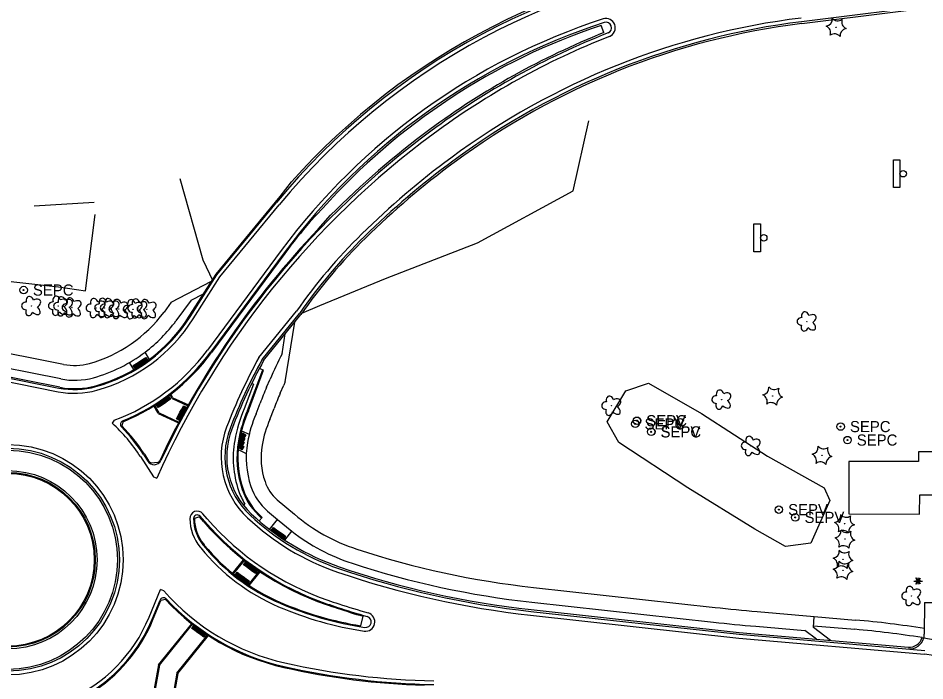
# Model space of a CAD drawing. Extents: x 588843 to 2552415, y 180129 to 269402.
# Drawn here: x 590641.6 to 591129.5, y 186685.9 to 187042.7 of the extents above; entities that cross this region are included whole.
import ezdxf

# ---------------------------------------------------------------- set-up
doc = ezdxf.new("R2010")
doc.units = 0
for name, color, linetype in [('E_BLD', 7, 'Continuous'), ('E_LAND_TreeLine', 7, 'Continuous'), ('E_LAND_Vegetation', 7, 'Continuous'), ('E_LTG', 7, 'Continuous'), ('E_MISCPROP_Septic', 7, 'Continuous'), ('E_MISCPROP_YardLight', 7, 'Continuous'), ('E_RDWY_Gravel', 7, 'Continuous'), ('E_SGN', 7, 'Continuous'), ('P_DWY', 7, 'Continuous'), ('P_PATH_Sidewalk', 7, 'Continuous'), ('P_RDWY_C_and_G_30', 7, 'Continuous'), ('P_RDWY_C_and_G_36', 7, 'Continuous'), ('P_RDWY_C_and_GBack', 7, 'Continuous'), ('P_RDWY_C_and_GFace', 7, 'Continuous'), ('P_RDWY_LaneEdge', 7, 'Continuous')]:
    doc.layers.add(name, color=color, linetype=linetype)

# ---------------------------------------------------------------- blocks, each defined once
blk = doc.blocks.new('CTRE_2')
at = {"layer": 'E_LAND_Vegetation'}
blk.add_circle((0, 0), 0.223, dxfattribs=at)
for centre, start, end in [((-11.97, 8.96), 280.2067, 5.97162), ((1.81, 14.92), 220.21132, 305.97623), ((-13.83, -5.9), 340.21132, 65.97623), ((13.83, 5.89), 160.21133, 245.97624), ((-1.81, -14.93), 40.21133, 125.97624), ((12.03, -9.04), 100.25111, 185.92721)]:
    blk.add_arc(centre, 7.87, start, end, dxfattribs=at)
blk = doc.blocks.new('DTRE_2')
at = {"layer": 'E_LAND_Vegetation'}
blk.add_circle((-0.18, 0), 0.183, dxfattribs=at)
for centre, major_axis, ratio in [((-1.87, 5.32), (1.36, -4.98), 0.782863), ((-5.87, 0.15), (4.93, -0.12), 0.832022), ((4.06, 2.74), (-5.27, -2.93), 0.691916), ((-2.49, -5.24), (1.8, 4.86), 0.716896), ((3.54, -3.71), (-5.01, 4.58), 0.560249)]:
    blk.add_ellipse(centre, major_axis=major_axis, ratio=ratio, start_param=1.570796, end_param=4.712389, dxfattribs=at)
blk = doc.blocks.new('LPOL_2')
at = {"layer": 'E_LTG'}
for p, q in [((-4, 0), (-1.5, 0)), ((-0.75, 1.3), (-2, 3.46)), ((0.75, 1.3), (2, 3.46)), ((1.5, 0), (4, 0)), ((-2, -3.46), (-0.75, -1.3)), ((2, -3.46), (0.75, -1.3))]:
    blk.add_line(p, q, dxfattribs=at)
for radius in [1.5, 1.5, 1.5, 0.125]:
    blk.add_circle((0, 0), radius, dxfattribs=at)
blk = doc.blocks.new('SEPC')
at = {"layer": 'E_MISCPROP_Septic'}
for radius in [4, 0.5]:
    blk.add_circle((0, 0), radius, dxfattribs=at)
blk.add_text('SEPC', height=12, dxfattribs=at).set_placement((10, -6))
blk = doc.blocks.new('SEPV')
at = {"layer": 'E_MISCPROP_Septic'}
for radius in [4, 0.5]:
    blk.add_circle((0, 0), radius, dxfattribs=at)
blk.add_text('SEPV', height=12, dxfattribs=at).set_placement((10, -6))
blk = doc.blocks.new('SGN')
at = {"layer": 'E_SGN'}
blk.add_lwpolyline([(-3.5, -15), (-10.5, -15), (-10.5, 15), (-3.5, 15)], close=True, dxfattribs=at)
blk.add_circle((0, 0), 3.5, dxfattribs=at)
blk = doc.blocks.new('RAMPD_1')
at = {"layer": 'P_PATH_Sidewalk'}
for p, q in [((-0.01, 0), (-0.01, 0.02)), ((-0.01, 0.02), (0.01, 0.02)), ((0.01, 0), (-0.01, 0)), ((0.01, 0.02), (0.01, 0))]:
    blk.add_line(p, q, dxfattribs=at)
for centre in [(-0.0075, 0.0175), (-0.0075, 0.0137), (-0.0075, 0.01), (-0.0075, 0.0062), (-0.0075, 0.0025), (-0.0037, 0.0175), (-0.0037, 0.0137), (-0.0037, 0.01), (-0.0037, 0.0062), (-0.0037, 0.0025), (0, 0.0175), (0, 0.0137), (0, 0.01), (0, 0.0062), (0, 0.0025), (0.0038, 0.0175), (0.0038, 0.0137), (0.0038, 0.01), (0.0038, 0.0062), (0.0038, 0.0025), (0.0075, 0.0175), (0.0075, 0.0137), (0.0075, 0.01), (0.0075, 0.0062), (0.0075, 0.0025)]:
    blk.add_circle(centre, 0.00125, dxfattribs=at)

msp = doc.modelspace()

# ---------------------------------------------------------------- linework, layer by layer
at = {"layer": 'E_BLD'}
msp.add_lwpolyline([(590682.52, 186943.34), (590650.19, 186941.49)], dxfattribs=at)
msp.add_lwpolyline([(591142.19, 186809.23), (591126.11, 186809.29), (591126.08, 186804), (591088.64, 186804.02), (591088.48, 186775.91), (591088.48, 186775.9), (591126.66, 186775.73), (591126.73, 186786), (591142.01, 186786.04)], close=True, dxfattribs=at)
at = {"layer": 'E_LAND_TreeLine'}
for points in [[(590794.26, 186883.86), (590804, 186888.02), (590839.27, 186902.57), (590888.67, 186921.7), (590940.25, 186949.76), (590948.66, 186987.38)], [(590728.5, 186956.4), (590740.87, 186912.64), (590746.29, 186901.31)]]:
    msp.add_lwpolyline(points, dxfattribs=at)
at = {"layer": 'E_MISCPROP_Septic'}
msp.add_lwpolyline([(591037.97, 186767.55), (591001.85, 186789.88), (590964.8, 186814.16), (590958.54, 186825.27), (590968.64, 186842.04), (590980.73, 186846.16), (591009.2, 186829.87), (591044.76, 186806.95), (591075.3, 186789.75), (591078.29, 186783.05), (591068.19, 186760.11), (591054.5, 186758.23)], close=True, dxfattribs=at)
at = {"layer": 'E_RDWY_Gravel'}
msp.add_lwpolyline([(590503.84, 186888.11), (590515.32, 186892.37), (590571.93, 186894.96), (590593.36, 186895.68), (590629.65, 186901.83), (590663.34, 186898.08), (590677.82, 186895.83), (590683.07, 186936.89)], dxfattribs=at)
at = {"layer": 'P_DWY'}
for points in [[(591129.19, 186728.06), (591129.18, 186711.06)], [(591129.19, 186728.06), (591141.11, 186728.08)], [(591128.92, 186709.05), (591141.16, 186706.9)]]:
    msp.add_lwpolyline(points, dxfattribs=at)
for start, end in [(265.0417, 345.4333), (345.4333, 359.9711)]:
    msp.add_arc((591121.18, 186711.06), 8, start, end, dxfattribs=at)
at = {"layer": 'P_PATH_Sidewalk'}
for p, q in [((590723.97, 186889.71), (590745.63, 186901.04)), ((590734.75, 186890.83), (590741.35, 186894.28)), ((590785.28, 186846.98), (590790.37, 186878.96)), ((590783.61, 186861.94), (590785.33, 186872.75)), ((590712.18, 186858.98), (590709.9, 186862.9)), ((590703.83, 186853.45), (590701.57, 186857.34)), ((590724.43, 186837.96), (590723.29, 186839.92)), ((590724.43, 186837.96), (590732.91, 186834.02)), ((590717.37, 186830.22), (590715.05, 186834.19)), ((590717.37, 186830.22), (590728.12, 186825.22)), ((590761.78, 186820.6), (590765.93, 186818.66)), ((590759.98, 186810.4), (590764.36, 186808.37)), ((590781.01, 186783.45), (590790.23, 186775.62)), ((590775.83, 186777.35), (590781.18, 186772.81)), ((590776.86, 186767.48), (590781.18, 186772.81)), ((590785.03, 186761.68), (590788.88, 186766.42)), ((590757.37, 186743.46), (590763.31, 186750.78)), ((590765.43, 186737.52), (590771.43, 186744.91)), ((591069.46, 186714.61), (591069.86, 186720.6)), ((590717.58, 186694.4), (590735.4, 186716.38)), ((591078.78, 186707.71), (591069.46, 186714.61)), ((590726.97, 186690.11), (590743.55, 186710.55)), ((591071.16, 186708.38), (591064.91, 186713)), ((590717.58, 186694.4), (590712.48, 186665.67)), ((590726.97, 186690.11), (590722.35, 186664.07))]:
    msp.add_line(p, q, dxfattribs=at)
for points in [[(590723.97, 186889.71), (590720.08, 186884.45)], [(590734.75, 186890.83), (590726.51, 186879.69)], [(590666.03, 186856.29), (590573.06, 186874.79)], [(590664.47, 186848.45), (590664.47, 186848.45), (590570.02, 186867.24)], [(590775.26, 186843.97), (590777.12, 186848.29)], [(590782.6, 186840.8), (590784.47, 186845.12)], [(590769.61, 186829.63), (590771.78, 186835.36)], [(590777.03, 186826.62), (590779.26, 186832.53)], [(590781.18, 186772.81), (590788.88, 186766.42)], [(590918.87, 186736.23), (591016.58, 186725.48)], [(590918, 186728.27), (591015.71, 186717.53)], [(591039.25, 186723.26), (591069.86, 186720.6)], [(591069.86, 186720.6), (591092.2, 186718.66)], [(591038.56, 186715.29), (591064.91, 186713)], [(591069.52, 186715.61), (591091.77, 186713.68)]]:
    msp.add_lwpolyline(points, dxfattribs=at)
for centre, radius, start, end in [((590659.79, 186929.06), 75, 285.593, 323.5041), ((590659.79, 186929.06), 83, 307.1416, 323.5041), ((590659.79, 186929.06), 83, 285.593, 307.1416), ((590968.1, 186765.87), 208, 152.491, 156.6561), ((590671.89, 186885.72), 30, 258.747, 285.593), ((590671.89, 186885.72), 38, 258.747, 285.593), ((590968.1, 186765.87), 200, 156.0748, 156.6561), ((590958.89, 186764.72), 200, 156.6561, 159.3176), ((590958.89, 186764.72), 192, 156.6561, 159.3176), ((590832, 186802.58), 68, 156.56, 170.1686), ((590832, 186802.58), 60, 156.3818, 170.1686), ((590812.3, 186806), 48, 170.1684, 198.7153), ((590812.3, 186806), 40, 170.1684, 198.7153), ((590795.25, 186800.22), 22, 198.7153, 229.669), ((590795.25, 186800.22), 30, 198.7153, 229.669), ((590854.95, 186851.85), 100, 229.669, 251.8118), ((590854.95, 186851.85), 108, 232.2824, 251.8118), ((590970.13, 187202.42), 469, 251.8118, 263.7259), ((590970.13, 187202.42), 477, 251.8118, 263.7259), ((591124.99, 187711.54), 992, 263.72585, 265.04172), ((591048.56, 186215.55), 505, 80.8131, 85.0417), ((591124.99, 187711.54), 1000, 263.72585, 265.04172), ((591048.56, 186215.55), 500, 80.8657, 85.0417)]:
    msp.add_arc(centre, radius, start, end, dxfattribs=at)
at = {"layer": 'P_RDWY_C_and_G_30'}
for p, q in [((590741.43, 186771.53), (590739.08, 186774.25)), ((590772.92, 186773.92), (590771.29, 186772.02)), ((590756.99, 186743.78), (590762.92, 186751.09)), ((590765.85, 186737.24), (590771.84, 186744.63)), ((590714.31, 186719.24), (590718.37, 186729.22)), ((590718.48, 186729.43), (590720.68, 186729.83)), ((590917.56, 186724.3), (591029.6, 186711.98))]:
    msp.add_line(p, q, dxfattribs=at)
for points in [[(591029.59, 186711.98), (591120.58, 186704.09)], [(591127.93, 186709.21), (591128.92, 186709.05)]]:
    msp.add_lwpolyline(points, dxfattribs=at)
for centre, radius, start, end in [((590812.3, 186806), 52.5, 170.1684, 198.7153), ((590795.25, 186800.22), 34.5, 198.7153, 229.669), ((590758.94, 186773.58), 22.5, 180.8337, 218.8926), ((590856.79, 186871.28), 131, 226.7487, 251.1047), ((590856.79, 186871.28), 152.5, 220.8517, 251.1047), ((590755.31, 186770.11), 17.5, 217.5597, 219.1596), ((590825.1, 186826.94), 107.5, 219.1592, 246.7759), ((590970.13, 187202.42), 481, 251.1047, 263.7259), ((590719.76, 186728.65), 1.5, 148.6217, 157.8313), ((590719.76, 186728.65), 1.5, 43.0326, 52.2423), ((590855.86, 186898.62), 185.5, 246.776, 260.7412), ((590970.13, 187202.42), 502.5, 251.1047, 251.81), ((590970.13, 187202.42), 502.5, 251.81, 253.4684), ((591121.18, 186711.06), 7, 265.0417, 344.6627)]:
    msp.add_arc(centre, radius, start, end, dxfattribs=at)
at = {"layer": 'P_RDWY_C_and_G_36'}
for radius in [59, 48, 46.5]:
    msp.add_circle((590636.05, 186751.12), radius, dxfattribs=at)
at = {"layer": 'P_RDWY_C_and_GBack'}
for p, q in [((590782.55, 186946.68), (590788.72, 186954.55)), ((590748.04, 186904.83), (590782.55, 186946.68)), ((590798.63, 186933.15), (590805.55, 186940.37)), ((590803.05, 186929.06), (590809.66, 186936.56)), ((590733.68, 186882.19), (590748.04, 186904.83)), ((590773.66, 186858.35), (590793.71, 186883.08)), ((590773.67, 186853.12), (590771.32, 186854.01)), ((590724.78, 186838.35), (590723.69, 186840.23)), ((590724.78, 186838.35), (590733.16, 186834.46)), ((590717.01, 186829.83), (590714.63, 186833.93)), ((590717.01, 186829.83), (590727.88, 186824.78)), ((590709.5, 186807.97), (590711.8, 186804.39)), ((590716.74, 186803.41), (590713.14, 186803.17)), ((590739.08, 186774.25), (590736.44, 186773.25)), ((590717.11, 186694.62), (590735.01, 186716.69)), ((590727.44, 186689.89), (590743.97, 186710.27)), ((590717.11, 186694.62), (590711.98, 186665.76)), ((590727.44, 186689.89), (590722.84, 186664))]:
    msp.add_line(p, q, dxfattribs=at)
for points in [[(591063.26, 187039.74), (591164.09, 187052.27)], [(591063.26, 187039.74), (591164.09, 187052.27)], [(590956.73, 187034.85), (590955.33, 187038.74)], [(590785.11, 186916.03), (590745.66, 186862.7)], [(590664.03, 186843.95), (590570.62, 186862.53)], [(590765.44, 186831.32), (590773.67, 186853.12)], [(590697.82, 186825.29), (590697.38, 186823.09)], [(590826.01, 186715.54), (590827.15, 186720.69)]]:
    msp.add_lwpolyline(points, dxfattribs=at)
for centre, radius, start, end in [((591064.47, 186709.34), 369, 95.6887, 138.3547), ((591064.47, 186709.34), 347, 108.3315, 138.2586), ((591112.21, 186645.77), 397, 97.0822, 126.4881), ((591112.21, 186645.77), 419, 111.7822, 126.4881), ((591141.94, 186605.57), 469, 126.4881, 135.1112), ((591141.94, 186605.57), 447, 126.4881, 134.5027), ((591064.47, 186709.34), 347.5, 139.9066, 143.5041), ((591141.94, 186605.57), 468.5, 136.332, 154.834), ((591033.99, 186715.41), 293, 134.5027, 145.0921), ((590659.79, 186929.06), 87.5, 285.593, 327.6145), ((590655.02, 186929.35), 112.51, 292.4636, 323.6755), ((591033.99, 186715.41), 297, 151.23, 159.0808), ((590671.88, 186885.76), 42.55, 259.3663, 285.5858), ((590832, 186802.58), 72.5, 156.6469, 170.1686), ((590698.58, 186823.99), 1.5, 216.7381, 224.6337), ((590631.69, 186757.95), 92.5, 32.7372, 44.6338), ((590698.58, 186823.99), 1.5, 112.4631, 120.3589), ((590795.8, 186806.46), 42, 159.0808, 226.7487), ((590714.74, 186806.29), 3.5, 212.7372, 242.7829), ((590714.74, 186806.29), 3.5, 304.7883, 334.834), ((590811.86, 186814.63), 124.5, 223.0326, 257.3172), ((590636.05, 186751.12), 84.5, 301.581, 337.8314), ((590872.9, 187085.85), 402.5, 257.3172, 268.1757)]:
    msp.add_arc(centre, radius, start, end, dxfattribs=at)
at = {"layer": 'P_RDWY_C_and_GFace'}
for p, q in [((591163.96, 187053.26), (591063.14, 187040.73)), ((590748.44, 186904.53), (590780.55, 186943.47)), ((590784.71, 186916.32), (590745.23, 186862.96)), ((590734.1, 186881.93), (590748.44, 186904.53)), ((590772.82, 186858.91), (590792.91, 186883.68)), ((590570.53, 186862.04), (590663.49, 186843.54)), ((590709.08, 186807.7), (590711.38, 186804.12)), ((590741.81, 186771.85), (590739.46, 186774.58)), ((590713.84, 186719.42), (590717.91, 186729.4)), ((590917.45, 186723.3), (591029.51, 186710.99))]:
    msp.add_line(p, q, dxfattribs=at)
for points in [[(590764.98, 186831.51), (590773.2, 186853.29)], [(591029.51, 186710.99), (591129.47, 186702.31)]]:
    msp.add_lwpolyline(points, dxfattribs=at)
for radius in [60, 47]:
    msp.add_circle((590636.05, 186751.12), radius, dxfattribs=at)
for centre, radius, start, end in [((591064.47, 186709.34), 368, 95.6887, 140.4896), ((591064.47, 186709.34), 348, 107.991, 143.5041), ((591112.21, 186645.77), 398, 97.0822, 126.4881), ((590957.91, 187037.48), 3, 291.4998, 107.9919), ((591112.21, 186645.77), 418, 111.5002, 126.4881), ((591141.94, 186605.57), 468, 126.4881, 154.834), ((591141.94, 186605.57), 448, 126.4881, 134.5027), ((591033.99, 186715.41), 294, 134.5027, 145.085), ((590659.79, 186929.06), 88, 285.593, 327.6145), ((590655.02, 186929.34), 112, 292.4632, 323.6491), ((591033.99, 186715.41), 298, 151.2127, 159.0808), ((590671.89, 186885.72), 43, 258.747, 285.593), ((590832, 186802.58), 73, 156.6561, 170.1686), ((590698.58, 186823.99), 2, 112.4632, 224.6338), ((590631.69, 186757.95), 92, 32.7372, 44.6338), ((590795.8, 186806.46), 43, 159.0808, 226.7487), ((590812.3, 186806), 53, 170.1684, 198.7153), ((590714.74, 186806.29), 4, 212.7372, 334.834), ((590795.25, 186800.22), 35, 198.7153, 229.669), ((590737.94, 186773.27), 2, 40.8517, 180.8337), ((590758.94, 186773.58), 23, 180.8337, 218.8926), ((590856.79, 186871.28), 132, 226.7487, 251.1047), ((590856.79, 186871.28), 152, 220.8517, 251.1047), ((590720.19, 186741.92), 27.04, 38.4934, 39.5584), ((590825.1, 186826.94), 108, 219.1592, 246.7759), ((590970.13, 187202.42), 482, 251.1047, 263.7259), ((590719.76, 186728.65), 2, 43.0326, 157.8313), ((590811.86, 186814.63), 124, 223.0326, 257.3172), ((590855.86, 186898.62), 186, 246.776, 261.4121), ((590970.13, 187202.42), 502, 251.1047, 251.81), ((590970.13, 187202.42), 502, 251.81, 253.7162), ((590636.05, 186751.12), 84, 301.581, 337.8314), ((590828.53, 186717.68), 3, 261.4116, 73.7162), ((590872.9, 187085.85), 402, 257.3172, 268.9055)]:
    msp.add_arc(centre, radius, start, end, dxfattribs=at)
at = {"layer": 'P_RDWY_LaneEdge'}
for p, q in [((590750.06, 186903.36), (590782.1, 186942.2)), ((590783.1, 186917.51), (590743.45, 186863.92)), ((590735.79, 186880.85), (590750.06, 186903.36)), ((590771.16, 186860.03), (590791.32, 186884.88)), ((590570.14, 186860.08), (590663.1, 186841.58)), ((590707.39, 186806.62), (590714.35, 186795.8)), ((590714.35, 186795.8), (590716.17, 186794.99)), ((590762.71, 186780.59), (590763.57, 186781.11)), ((590743.33, 186773.16), (590740.97, 186775.89)), ((590719.95, 186734.41), (590718.1, 186735.16)), ((590917.24, 186721.32), (591029.31, 186708.99))]:
    msp.add_line(p, q, dxfattribs=at)
for points in [[(590768.15, 186845.57), (590763.14, 186832.3)], [(590768.15, 186845.57), (590767.24, 186845.98)], [(590693.32, 186826.22), (590692.11, 186824.63)], [(590711.99, 186720.18), (590718.1, 186735.16)], [(591029.31, 186708.99), (591129.22, 186700.33)]]:
    msp.add_lwpolyline(points, dxfattribs=at)
msp.add_circle((590636.05, 186751.12), 62, dxfattribs=at)
for centre, radius, start, end in [((591064.47, 186709.34), 366, 95.6887, 140.4896), ((591064.47, 186709.34), 350, 107.991, 143.5041), ((591112.21, 186645.77), 400, 97.0822, 126.4881), ((590957.91, 187037.48), 5, 291.5002, 107.991), ((591112.21, 186645.77), 416, 111.5002, 126.4881), ((591141.94, 186605.57), 466, 126.4881, 156.0164), ((591141.94, 186605.57), 450, 126.4881, 134.5027), ((591033.99, 186715.41), 296, 134.5027, 145.071), ((590659.79, 186929.06), 90, 285.593, 327.6145), ((590655.02, 186929.34), 110, 290.3756, 323.5043), ((591033.99, 186715.41), 300, 151.1784, 159.0808), ((590671.89, 186885.72), 45, 258.747, 285.593), ((590832, 186802.58), 75, 156.6561, 170.1686), ((590631.69, 186757.95), 90, 32.7372, 47.8225), ((590795.8, 186806.46), 45, 159.0808, 226.7487), ((590812.3, 186806), 55, 170.1684, 198.7153), ((590795.25, 186800.22), 37, 198.7153, 211.1044), ((590737.94, 186773.27), 4, 40.8517, 180.8337), ((590758.94, 186773.58), 25, 180.8337, 218.8926), ((590856.79, 186871.28), 150, 220.8517, 251.1047), ((590856.79, 186871.28), 134, 226.7487, 251.1047), ((590755.31, 186770.11), 20, 217.693, 219.1591), ((590825.1, 186826.94), 110, 219.1591, 246.7759), ((590970.13, 187202.42), 484, 251.1047, 263.7259), ((590811.86, 186814.63), 122, 221.1148, 257.3172), ((590970.13, 187202.42), 500, 251.1047, 251.81), ((590855.86, 186898.62), 188, 246.776, 261.4121), ((590970.13, 187202.42), 500, 251.81, 253.7162), ((590636.05, 186751.12), 82, 293.0446, 337.8313), ((590828.53, 186717.68), 5, 261.4121, 73.7162), ((590930.51, 185484.46), 1232, 77.08863, 80.71822), ((590872.9, 187085.85), 400, 257.3172, 268.9055)]:
    msp.add_arc(centre, radius, start, end, dxfattribs=at)

# ---------------------------------------------------------------- block references
at = {"layer": 'E_LAND_Vegetation', "xscale": 0.5, "yscale": 0.5}
for name, p in [('CTRE_2', (591081.73, 187037.69)), ('DTRE_2', (590648.86, 186887.65)), ('DTRE_2', (590663.26, 186887.78)), ('DTRE_2', (590666.05, 186887.47)), ('DTRE_2', (590670.58, 186886.88)), ('DTRE_2', (590683.5, 186886.57)), ('DTRE_2', (590688.12, 186886.66)), ('DTRE_2', (590691.17, 186886.56)), ('DTRE_2', (590695.81, 186886.05)), ('DTRE_2', (590703.49, 186885.94)), ('DTRE_2', (590705.98, 186886.32)), ('DTRE_2', (590710.99, 186885.99)), ('DTRE_2', (591066.1, 186879.35)), ('DTRE_2', (591020.24, 186837.29)), ('CTRE_2', (591047.6, 186839.22)), ('DTRE_2', (590960.98, 186833.99)), ('DTRE_2', (591036.05, 186812.36)), ('CTRE_2', (591074.12, 186807.3)), ('CTRE_2', (591086.24, 186770.48)), ('CTRE_2', (591086.46, 186762.23)), ('CTRE_2', (591085.48, 186751.3)), ('CTRE_2', (591085.39, 186745.42)), ('DTRE_2', (591122.39, 186731.55))]:
    msp.add_blockref(name, p, dxfattribs=at)
at = {"layer": 'E_LTG', "xscale": 0.5, "yscale": 0.5}
msp.add_blockref('LPOL_2', (591125.57, 186739.67), dxfattribs=at)
at = {"layer": 'E_MISCPROP_Septic', "xscale": 0.5, "yscale": 0.5}
for name, p in [('SEPC', (590644.53, 186896.3)), ('SEPV', (590973.62, 186824.26)), ('SEPC', (590973.66, 186824.25)), ('SEPV', (590974.51, 186825.96)), ('SEPC', (590974.59, 186825.96)), ('SEPC', (591084.16, 186822.8)), ('SEPC', (590982.22, 186819.95)), ('SEPV', (590982.26, 186820.02)), ('SEPC', (591087.83, 186815.55)), ('SEPV', (591050.91, 186778.09)), ('SEPV', (591059.74, 186773.93))]:
    msp.add_blockref(name, p, dxfattribs=at)
at = {"layer": 'E_MISCPROP_YardLight', "xscale": 0.5, "yscale": 0.5}
msp.add_blockref('LPOL_2', (591126.13, 186739.68), dxfattribs=at)
at = {"layer": 'E_SGN', "xscale": 0.5, "yscale": 0.5}
for p in [(591117.78, 186958.94), (591042.76, 186924.39)]:
    msp.add_blockref('SGN', p, dxfattribs=at)
at = {"layer": 'P_PATH_Sidewalk'}
for p, xscale, yscale, rotation in [((590709.37, 186859.51), 100.00000000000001, 100.00000000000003, -146.47954105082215), ((590704.37, 186856.19), 100.00000000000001, 100.00000000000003, -146.47954105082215), ((590706.03, 186857.3), 100.00000000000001, 100.00000000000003, -146.47954105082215), ((590707.7, 186858.41), 100.00000000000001, 100.00000000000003, -146.47954105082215), ((590716.68, 186835.21), 99.99999999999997, 99.99999999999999, -145.49339663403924), ((590718.33, 186836.34), 99.99999999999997, 99.99999999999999, -145.49339663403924), ((590719.98, 186837.48), 99.99999999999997, 99.99999999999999, -145.49339663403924), ((590721.63, 186838.61), 99.99999999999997, 99.99999999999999, -145.49339663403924), ((590729.12, 186831.37), 99.99999999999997, 99.99999999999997, -118.87657015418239), ((590730.09, 186833.12), 99.99999999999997, 99.99999999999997, -118.87657015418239), ((590727.19, 186827.86), 99.99999999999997, 99.99999999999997, -118.87657015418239), ((590728.16, 186829.62), 99.99999999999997, 99.99999999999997, -118.87657015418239), ((590761.39, 186816.42), 99.99999999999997, 99.99999999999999, -120.31665227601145), ((590761.81, 186818.49), 99.99999999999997, 99.99999999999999, -120.31665227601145), ((590760.78, 186812.15), 99.99999999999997, 99.99999999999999, -120.31665227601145), ((590761.01, 186814.33), 99.99999999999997, 99.99999999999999, -120.31665227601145), ((590779.73, 186767.88), 100, 99.99999999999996, 144.6866658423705), ((590781.36, 186766.72), 100, 99.99999999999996, 144.6866658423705), ((590782.99, 186765.57), 100, 99.99999999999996, 144.6866658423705), ((590784.63, 186764.41), 100, 99.99999999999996, 144.6866658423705), ((590764.84, 186749.45), 99.99999999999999, 99.99999999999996, 142.97066296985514), ((590766.43, 186748.24), 99.99999999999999, 99.99999999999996, 142.97066296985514), ((590768.03, 186747.04), 99.99999999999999, 99.99999999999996, 142.97066296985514), ((590760.32, 186743.84), 99.99999999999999, 99.99999999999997, 143.68014303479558), ((590761.93, 186742.66), 99.99999999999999, 99.99999999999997, 143.68014303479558), ((590769.63, 186745.84), 99.99999999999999, 99.99999999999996, 142.97066296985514), ((590763.55, 186741.47), 99.99999999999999, 99.99999999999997, 143.68014303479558), ((590765.16, 186740.29), 99.99999999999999, 99.99999999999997, 143.68014303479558), ((590736.93, 186715.16), 100, 99.99999999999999, 144.37923940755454), ((590738.56, 186714), 100, 99.99999999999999, 144.37923940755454), ((590740.19, 186712.83), 100, 99.99999999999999, 144.37923940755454), ((590741.81, 186711.67), 100, 99.99999999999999, 144.37923940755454)]:
    msp.add_blockref('RAMPD_1', p, dxfattribs=dict(at, xscale=xscale, yscale=yscale, rotation=rotation))

doc.saveas('drawing.dxf')
